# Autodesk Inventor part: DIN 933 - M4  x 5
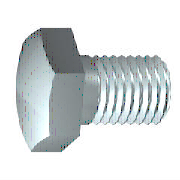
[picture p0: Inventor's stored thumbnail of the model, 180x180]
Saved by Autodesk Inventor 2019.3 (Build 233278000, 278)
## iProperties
Created: 2018-01
Part Number: DIN 933 - M4  x 5
Material: Ocel, měkká
Description: Šestihranný šroub
Document SubType Name: Modeling
Standard: DIN 933
Designer: B-hon
Standards Organization: DIN
Language: cs-CZ
Size Designation: M4  x 5
Categories: <MemberInstance><Categories><Category DisplayName="Spojovací materiál" InternalName="e4da775c-781d-43d5-af7c-5136215cf5a6" Mnemonic="FSTN"><Category DisplayName
Density: 7.85 g/cm^3
Appearance: Pololeštěná
IsCustomPart: 0
Author: B-hon
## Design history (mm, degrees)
sketch "Náčrt1"
  geometry: L1 (0, 2.95)-(0, 1.811); L2 (2.1, 2)-(5, 2); L3 (5, 2)-(5, 0); L4 (5, 0)-(-0.4, 0); L5 (-1.48, 0)-(6.08, 0) reference; L6 (-0.4, 0)-(-0.4, 2.95); L7 (-0.4, 2.95)-(0, 2.95); L8 (2.1, 2)-(1.67, 1.811); L9 (1.67, 1.811)-(0, 1.811); L10 (0, -0.59)-(0, 3.54) reference
  constraints: 16 end point, 2 collinear, 2 perpendicular, 1 parallel
  dimensions: "d0" = 5 distance between parallel lines of L3 L1 (= NLG); "d1" = 2.9 distance from line of L2.start L3 (= GEL); "d2" = 4 diameter of L2 L4 (= GD); "d9" = 0.4001 distance between parallel lines of L6 L1 (computed from SD); "d10" = 5.9 diameter of L7 L4 (= SD2); "d13" = 0.42952 horizontal distance of L2.start L8.end (computed from GAL); "d14" = 3.62111 diameter of L9 L4 (= BDM)
revolve "Těleso" sketch "Náčrt1" stored, may be unused: angle "d12" = 90 deg
sketch "Náčrt2"
  geometry: L1 (0, 4.041)-(3.5, 2.021); L2 (3.5, 2.021)-(3.5, -2.021); L3 (3.5, -2.021)-(0, -4.041); L4 (0, -4.041)-(-3.5, -2.021); L5 (-3.5, -2.021)-(-3.5, 2.021); L6 (-3.5, 2.021)-(0, 4.041); 2 further points
  constraints: 12 end point, 1 coincident, 1 vertical, 11 other
  dimensions: "d11" = 7 distance between parallel lines of L5 L2 (= SW)
extrude "Hlava" join sketch "Náčrt2" distance "d3" = 2.4 (= KOH - SD); taper "d4" = 0 deg
sketch "Náčrt4"
  geometry: L1 (-2.8, 3.5)-(-2.8, 4.041); L2 (-2.8, 4.041)-(-2.487, 4.041); L3 (-2.487, 4.041)-(-2.8, 3.5); L4 (-3.28, 0)-(0.08, 0) reference; L5 (-0.4, 4.041)-(-2.8, 4.041) reference; L6 (-2.8, 2.021)-(-2.8, 4.041) reference
  constraints: 6 end point, 2 collinear, 1 perpendicular, 1 vertical
  dimensions: "d5" = 30 deg angle of L3 L1 (= ANG1); "d19" = 7 diameter of L1.start L4 (= SW0)
revolve "Zkosení1" sketch "Náčrt4" stored, may be unused: angle "d21" = 90 deg
workplane "Work Plane1"
body "Solid1"
feature "Závit" dims "d15" = 2.9 (= GEL), "d16" = 0
chamfer "Zkosení2" distance "d6" = 0.42941 (= -0.5 x SPD + 0.5 x GD); stored, may be unused: second distance "d7" = 0.42952 (computed from GUL), angle "d55" = 45 deg
other parameters: "NLG" = 5 [user parameter; used in 1 equation term], "GD" = 4 (= NND) [user parameter; used in 2 equation terms], "BDM" = 3.62111 [user parameter; used in 1 equation term], "KOH" = 2.8 [user parameter; used in 1 equation term], "GEL" = 2.9 [user parameter; used in 2 equation terms], "SW" = 7 [user parameter; used in 2 equation terms], "SW0" = 7 [user parameter; used in 1 equation term], "SPD" = 3.14117 (= NND - 1.2269 x PTC) [user parameter; used in 1 equation term], "SD2" = 5.9 [user parameter; used in 1 equation term], "SD" = 0.4 [user parameter; used in 2 equation terms], "ANG1" = 30 deg [user parameter; used in 1 equation term], "GAL" = 0.42941 (= 0.61345 x PTC) [user parameter; used in 1 equation term], "GUL" = 0.42941 (= 0.61345 x PTC) [user parameter; used in 1 equation term], "d8" = 0, "RR" = 0.2 [user parameter], "d57" = 0, "d58" = 0, "TPU" = 14.28571 (computed from PTC) [user parameter], "GD1" = 3.14117 (= THREADDIA - 1.2269 x PTC) [user parameter], "THREADDIA" = 4 [user parameter; used in 1 equation term], "TOA" = 30 deg [user parameter], "PTC" = 0.7 [user parameter; used in 5 equation terms], "NND" = 4 [user parameter; used in 2 equation terms], "E0" = 8.085 (= 1.155 x SW) [user parameter]
